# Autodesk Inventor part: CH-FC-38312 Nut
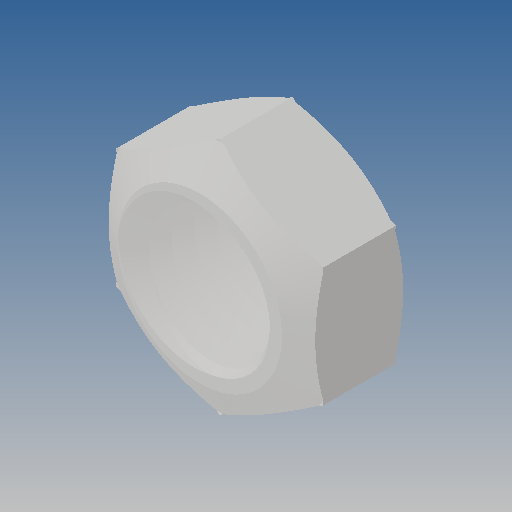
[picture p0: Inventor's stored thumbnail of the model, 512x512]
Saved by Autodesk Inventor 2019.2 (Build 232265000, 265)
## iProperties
Created: 2012-09
Part Number: CH-FC-38312 Nut
Material: Ogólny
Document SubType Name: Modeling
Designer: CADENGINEERING4
Density: 1 g/cm^3
Appearance: Domyślna
Author: CADENGINEERING4
Revision Number: ÈÎºÎ
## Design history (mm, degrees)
feature "ÇÐ³ý-É¨Ãè1"
node "Bryła1"
